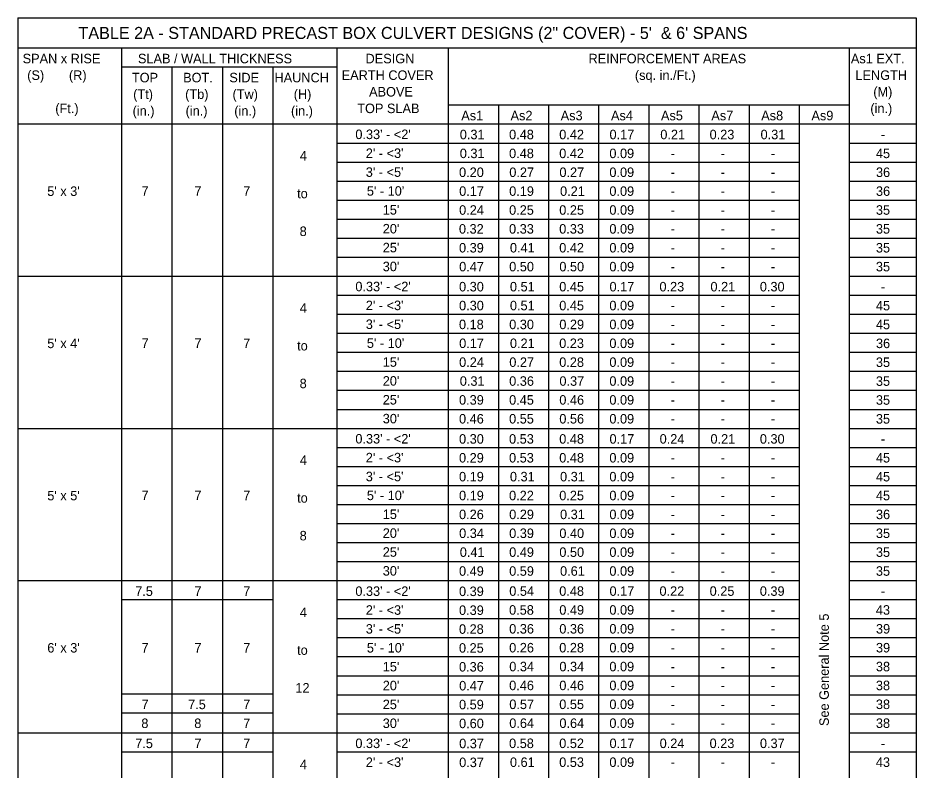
# Model space of a CAD drawing. Extents: x 10340.93 to 10343.14, y 76399.51 to 76400.59.
# Drawn here: x 10340.938 to 10341.533, y 76400.002 to 76400.5 of the extents above; entities that cross this region are included whole.
import ezdxf

# ---------------------------------------------------------------- set-up
doc = ezdxf.new("R2010")
doc.units = 0
doc.layers.add('AdhocPoint_dp', color=7, linetype='Continuous')
doc.layers.add('PlotBorder_dp', color=7, linetype='Continuous')

msp = doc.modelspace()

# ---------------------------------------------------------------- linework, layer by layer
at = {"layer": 'PlotBorder_dp'}
for p, q in [((10340.93815, 76400.49971), (10341.53289, 76400.49971)), ((10340.93815, 76400.49971), (10340.93815, 76399.72389)), ((10341.53289, 76400.49971), (10341.53289, 76399.72389)), ((10340.93815, 76400.47984), (10341.53289, 76400.47984)), ((10341.00679, 76400.47984), (10341.00679, 76399.72389)), ((10341.14923, 76400.47984), (10341.14923, 76399.72389)), ((10341.22311, 76400.47984), (10341.22311, 76399.72389)), ((10341.4887, 76400.47984), (10341.4887, 76399.72389)), ((10341.00679, 76400.46724), (10341.14923, 76400.46724)), ((10341.04015, 76400.46724), (10341.04015, 76399.72389)), ((10341.07351, 76400.46724), (10341.07351, 76399.72389)), ((10341.10687, 76400.46724), (10341.10687, 76399.72389)), ((10341.22311, 76400.44209), (10341.4887, 76400.44209)), ((10341.25631, 76400.44209), (10341.25631, 76399.72389)), ((10341.28951, 76400.44209), (10341.28951, 76399.72389)), ((10341.32271, 76400.44209), (10341.32271, 76399.72389)), ((10341.35591, 76400.44209), (10341.35591, 76399.72389)), ((10341.3891, 76400.44209), (10341.3891, 76399.72389)), ((10341.3891, 76400.44209), (10341.3891, 76399.72389)), ((10341.4223, 76400.44209), (10341.4223, 76399.72389)), ((10341.4555, 76400.44209), (10341.4555, 76399.72389)), ((10340.93815, 76400.42949), (10341.53289, 76400.42949)), ((10341.14923, 76400.41689), (10341.4555, 76400.41689)), ((10341.4887, 76400.41689), (10341.53289, 76400.41689)), ((10341.14923, 76400.40429), (10341.4555, 76400.40429)), ((10341.4887, 76400.40429), (10341.53289, 76400.40429)), ((10341.14923, 76400.39169), (10341.4555, 76400.39169)), ((10341.4887, 76400.39169), (10341.53289, 76400.39169)), ((10341.14923, 76400.37909), (10341.4555, 76400.37909)), ((10341.4887, 76400.37909), (10341.53289, 76400.37909)), ((10341.14923, 76400.36649), (10341.4555, 76400.36649)), ((10341.4887, 76400.36649), (10341.53289, 76400.36649)), ((10341.14923, 76400.35389), (10341.4555, 76400.35389)), ((10341.4887, 76400.35389), (10341.53289, 76400.35389)), ((10341.14923, 76400.34129), (10341.4555, 76400.34129)), ((10341.4887, 76400.34129), (10341.53289, 76400.34129)), ((10340.93815, 76400.32869), (10341.4555, 76400.32869)), ((10341.4887, 76400.32869), (10341.53289, 76400.32869)), ((10341.14923, 76400.31609), (10341.4555, 76400.31609)), ((10341.4887, 76400.31609), (10341.53289, 76400.31609)), ((10341.14923, 76400.30349), (10341.4555, 76400.30349)), ((10341.4887, 76400.30349), (10341.53289, 76400.30349)), ((10341.14923, 76400.29089), (10341.4555, 76400.29089)), ((10341.4887, 76400.29089), (10341.53289, 76400.29089)), ((10341.14923, 76400.27829), (10341.4555, 76400.27829)), ((10341.4887, 76400.27829), (10341.53289, 76400.27829)), ((10341.14923, 76400.26569), (10341.4555, 76400.26569)), ((10341.4887, 76400.26569), (10341.53289, 76400.26569)), ((10341.14923, 76400.25309), (10341.4555, 76400.25309)), ((10341.4887, 76400.25309), (10341.53289, 76400.25309)), ((10341.14923, 76400.24049), (10341.4555, 76400.24049)), ((10341.4887, 76400.24049), (10341.53289, 76400.24049)), ((10340.93815, 76400.22789), (10341.4555, 76400.22789)), ((10341.4887, 76400.22789), (10341.53289, 76400.22789)), ((10341.14923, 76400.21529), (10341.4555, 76400.21529)), ((10341.4887, 76400.21529), (10341.53289, 76400.21529)), ((10341.14923, 76400.20269), (10341.4555, 76400.20269)), ((10341.4887, 76400.20269), (10341.53289, 76400.20269)), ((10341.14923, 76400.19009), (10341.4555, 76400.19009)), ((10341.4887, 76400.19009), (10341.53289, 76400.19009)), ((10341.14923, 76400.17749), (10341.4555, 76400.17749)), ((10341.4887, 76400.17749), (10341.53289, 76400.17749)), ((10341.14923, 76400.16489), (10341.4555, 76400.16489)), ((10341.4887, 76400.16489), (10341.53289, 76400.16489)), ((10341.14923, 76400.15229), (10341.4555, 76400.15229)), ((10341.4887, 76400.15229), (10341.53289, 76400.15229)), ((10341.14923, 76400.13969), (10341.4555, 76400.13969)), ((10341.4887, 76400.13969), (10341.53289, 76400.13969)), ((10340.93815, 76400.12709), (10341.4555, 76400.12709)), ((10341.4887, 76400.12709), (10341.53289, 76400.12709)), ((10341.00679, 76400.11449), (10341.10687, 76400.11449)), ((10341.14923, 76400.11449), (10341.4555, 76400.11449)), ((10341.4887, 76400.11449), (10341.53289, 76400.11449)), ((10341.14923, 76400.10189), (10341.4555, 76400.10189)), ((10341.4887, 76400.10189), (10341.53289, 76400.10189)), ((10341.14923, 76400.08929), (10341.4555, 76400.08929)), ((10341.4887, 76400.08929), (10341.53289, 76400.08929)), ((10341.14923, 76400.07669), (10341.4555, 76400.07669)), ((10341.4887, 76400.07669), (10341.53289, 76400.07669)), ((10341.14923, 76400.06409), (10341.4555, 76400.06409)), ((10341.4887, 76400.06409), (10341.53289, 76400.06409)), ((10341.00679, 76400.05197), (10341.10687, 76400.05197)), ((10341.14923, 76400.05149), (10341.4555, 76400.05149)), ((10341.4887, 76400.05149), (10341.53289, 76400.05149)), ((10341.00679, 76400.03947), (10341.10687, 76400.03947)), ((10341.14923, 76400.03889), (10341.4555, 76400.03889)), ((10341.4887, 76400.03889), (10341.53289, 76400.03889)), ((10340.93815, 76400.02629), (10341.4555, 76400.02629)), ((10341.14985, 76400.02629), (10341.22203, 76400.02629)), ((10341.4887, 76400.02629), (10341.53289, 76400.02629)), ((10341.00679, 76400.01369), (10341.10687, 76400.01369)), ((10341.14923, 76400.01369), (10341.4555, 76400.01369)), ((10341.4887, 76400.01369), (10341.53289, 76400.01369))]:
    msp.add_line(p, q, dxfattribs=at)

# ---------------------------------------------------------------- texts
at = {"layer": 'AdhocPoint_dp'}
for s, height, p in [('TABLE 2A - STANDARD PRECAST BOX CULVERT DESIGNS (2" COVER) - 5\'  & 6\' SPANS', 0.008, (10340.97821, 76400.48578)), ('SLAB / WALL THICKNESS', 0.0063, (10341.01761, 76400.46968)), ('As1', 0.0063, (10341.23173, 76400.43192)), ('As2', 0.0063, (10341.26436, 76400.43192)), ('As3', 0.0063, (10341.29756, 76400.43192)), ('As4', 0.0063, (10341.33089, 76400.43192)), ('As5', 0.0063, (10341.36398, 76400.43192)), ('As7', 0.0063, (10341.39733, 76400.43192)), ('As8', 0.0063, (10341.43037, 76400.43192)), ('As9', 0.0063, (10341.46362, 76400.43192)), ("5' x 3'", 0.0063, (10340.95757, 76400.38182)), ("5' x 4'", 0.0063, (10340.95756, 76400.28104)), ("5' x 5'", 0.0063, (10340.95758, 76400.1802))]:
    msp.add_text(s, height=height, dxfattribs=at).set_placement(p)
msp.add_text('See General Note 5', height=0.0063, rotation=90, dxfattribs=at).set_placement((10341.47515, 76400.03075))
at = {"layer": 'PlotBorder_dp'}
for s, p in [('SPAN x RISE', (10340.94124, 76400.46968)), ('DESIGN', (10341.16833, 76400.46968)), ('REINFORCEMENT AREAS', (10341.31601, 76400.46968)), ('(S)       (R)', (10340.94428, 76400.45868)), ('EARTH COVER', (10341.15254, 76400.45868)), ('(sq. in./Ft.)', (10341.34671, 76400.45868)), ('TOP', (10341.01361, 76400.45708)), ('BOT.', (10341.04754, 76400.45708)), ('SIDE', (10341.07814, 76400.45708)), ('HAUNCH', (10341.10803, 76400.45708)), ('ABOVE', (10341.17068, 76400.44768)), ('(Tt)', (10341.01446, 76400.44608)), ('(Tb)', (10341.04888, 76400.44608)), ('(Tw)', (10341.08024, 76400.44608)), ('(H)', (10341.12077, 76400.44608)), ('(Ft.)', (10340.96286, 76400.43668)), ('(in.)', (10341.01407, 76400.43508)), ('(in.)', (10341.04916, 76400.43508)), ('(in.)', (10341.08139, 76400.43508)), ('(in.)', (10341.11896, 76400.43508)), ('TOP SLAB', (10341.16285, 76400.43668)), ("0.33' - <2'", (10341.16159, 76400.41948)), ('0.31', (10341.23075, 76400.41937)), ('0.48', (10341.2634, 76400.41937)), ('0.42', (10341.29659, 76400.41937)), ('0.17', (10341.32989, 76400.41937)), ('0.21', (10341.36354, 76400.41937)), ('0.23', (10341.39618, 76400.41937)), ('0.31', (10341.42994, 76400.41937)), ('-', (10341.50962, 76400.41937)), ('4', (10341.12481, 76400.40529)), ("2' - <3'", (10341.16849, 76400.40698)), ('0.31', (10341.23075, 76400.40687)), ('0.48', (10341.2634, 76400.40687)), ('0.42', (10341.29659, 76400.40687)), ('0.09', (10341.32981, 76400.40687)), ('45', (10341.50632, 76400.40687)), ('-', (10341.37038, 76400.40687)), ('-', (10341.40359, 76400.40687)), ('-', (10341.43677, 76400.40687)), ("3' - <5'", (10341.16849, 76400.39448)), ('0.20', (10341.23027, 76400.39437)), ('0.27', (10341.26353, 76400.39437)), ('0.27', (10341.29673, 76400.39437)), ('0.09', (10341.32981, 76400.39437)), ('36', (10341.50636, 76400.39437)), ('-', (10341.37038, 76400.39437)), ('-', (10341.40359, 76400.39437)), ('-', (10341.43677, 76400.39437)), ('7', (10341.01998, 76400.38198)), ('7', (10341.05502, 76400.38198)), ('7', (10341.08731, 76400.38192)), ("5' - 10'", (10341.1692, 76400.38198)), ('0.17', (10341.23033, 76400.38187)), ('0.19', (10341.26345, 76400.38187)), ('0.21', (10341.29715, 76400.38187)), ('0.09', (10341.32981, 76400.38187)), ('36', (10341.50636, 76400.38187)), ('to', (10341.12303, 76400.38029)), ('-', (10341.37038, 76400.38187)), ('-', (10341.40359, 76400.38187)), ('-', (10341.43677, 76400.38187)), ("15'", (10341.17972, 76400.36948)), ('0.24', (10341.23031, 76400.36937)), ('0.25', (10341.26341, 76400.36937)), ('0.25', (10341.29661, 76400.36937)), ('0.09', (10341.32981, 76400.36937)), ('35', (10341.50632, 76400.36937)), ('-', (10341.37038, 76400.36937)), ('-', (10341.40359, 76400.36937)), ('-', (10341.43677, 76400.36937)), ('8', (10341.1247, 76400.35529)), ("20'", (10341.17972, 76400.35698)), ('0.32', (10341.23019, 76400.35687)), ('0.33', (10341.26338, 76400.35687)), ('0.33', (10341.29658, 76400.35687)), ('0.09', (10341.32981, 76400.35687)), ('-', (10341.37038, 76400.35687)), ('-', (10341.40359, 76400.35687)), ('-', (10341.43677, 76400.35687)), ('35', (10341.50632, 76400.35687)), ("25'", (10341.17972, 76400.34448)), ('0.39', (10341.23025, 76400.34437)), ('0.41', (10341.26395, 76400.34437)), ('0.42', (10341.29659, 76400.34437)), ('0.09', (10341.32981, 76400.34437)), ('-', (10341.37038, 76400.34437)), ('-', (10341.40359, 76400.34437)), ('-', (10341.43677, 76400.34437)), ('35', (10341.50632, 76400.34437)), ("30'", (10341.17972, 76400.33198)), ('0.47', (10341.23033, 76400.33187)), ('0.50', (10341.26346, 76400.33187)), ('0.50', (10341.29667, 76400.33187)), ('0.09', (10341.32981, 76400.33187)), ('-', (10341.37038, 76400.33187)), ('-', (10341.40359, 76400.33187)), ('-', (10341.43677, 76400.33187)), ('35', (10341.50632, 76400.33187)), ("0.33' - <2'", (10341.16159, 76400.31869)), ('0.30', (10341.23027, 76400.31859)), ('0.51', (10341.26395, 76400.31859)), ('0.45', (10341.29661, 76400.31859)), ('0.17', (10341.32989, 76400.31859)), ('0.23', (10341.36297, 76400.31859)), ('0.21', (10341.39675, 76400.31859)), ('0.30', (10341.42945, 76400.31859)), ('-', (10341.50962, 76400.31854)), ('4', (10341.12481, 76400.30449)), ("2' - <3'", (10341.16849, 76400.30619)), ('0.30', (10341.23027, 76400.30609)), ('0.51', (10341.26395, 76400.30609)), ('0.45', (10341.29661, 76400.30609)), ('0.09', (10341.32981, 76400.30609)), ('45', (10341.50632, 76400.30604)), ('-', (10341.37038, 76400.30609)), ('-', (10341.40359, 76400.30609)), ('-', (10341.43677, 76400.30609)), ("3' - <5'", (10341.16849, 76400.29369)), ('0.18', (10341.23021, 76400.29359)), ('0.30', (10341.26346, 76400.29359)), ('0.29', (10341.29665, 76400.29359)), ('0.09', (10341.32981, 76400.29359)), ('45', (10341.50632, 76400.29354)), ('-', (10341.37038, 76400.29359)), ('-', (10341.40359, 76400.29359)), ('-', (10341.43677, 76400.29359)), ('7', (10341.01998, 76400.28114)), ('7', (10341.05502, 76400.28114)), ('7', (10341.08731, 76400.28109)), ("5' - 10'", (10341.1692, 76400.28119)), ('0.17', (10341.23033, 76400.28109)), ('0.21', (10341.26395, 76400.28109)), ('0.23', (10341.29658, 76400.28109)), ('0.09', (10341.32981, 76400.28109)), ('36', (10341.50636, 76400.28104)), ('to', (10341.12303, 76400.27949)), ('-', (10341.37038, 76400.28109)), ('-', (10341.40359, 76400.28109)), ('-', (10341.43677, 76400.28109)), ("15'", (10341.17972, 76400.26869)), ('0.24', (10341.23031, 76400.26859)), ('0.27', (10341.26353, 76400.26859)), ('0.28', (10341.2966, 76400.26859)), ('0.09', (10341.32981, 76400.26859)), ('35', (10341.50632, 76400.26854)), ('-', (10341.37038, 76400.26859)), ('-', (10341.40359, 76400.26859)), ('-', (10341.43677, 76400.26859)), ('8', (10341.1247, 76400.25449)), ("20'", (10341.17972, 76400.25619)), ('0.31', (10341.23075, 76400.25609)), ('0.36', (10341.26345, 76400.25609)), ('0.37', (10341.29673, 76400.25609)), ('0.09', (10341.32981, 76400.25609)), ('-', (10341.37038, 76400.25609)), ('-', (10341.40359, 76400.25609)), ('-', (10341.43677, 76400.25609)), ('35', (10341.50632, 76400.25604)), ("25'", (10341.17972, 76400.24369)), ('0.39', (10341.23025, 76400.24359)), ('0.45', (10341.26341, 76400.24359)), ('0.46', (10341.29665, 76400.24359)), ('0.09', (10341.32981, 76400.24359)), ('-', (10341.37038, 76400.24359)), ('-', (10341.40359, 76400.24359)), ('-', (10341.43677, 76400.24359)), ('35', (10341.50632, 76400.24354)), ("30'", (10341.17972, 76400.23119)), ('0.46', (10341.23025, 76400.23109)), ('0.55', (10341.26341, 76400.23109)), ('0.56', (10341.29665, 76400.23109)), ('0.09', (10341.32981, 76400.23109)), ('-', (10341.37038, 76400.23109)), ('-', (10341.40359, 76400.23109)), ('-', (10341.43677, 76400.23109)), ('35', (10341.50632, 76400.23104)), ("0.33' - <2'", (10341.16159, 76400.21786)), ('0.30', (10341.23027, 76400.21776)), ('0.53', (10341.26338, 76400.21776)), ('0.48', (10341.2966, 76400.21776)), ('0.17', (10341.32989, 76400.21776)), ('0.24', (10341.3631, 76400.21776)), ('0.21', (10341.39675, 76400.21776)), ('0.30', (10341.42945, 76400.21776)), ('-', (10341.50962, 76400.21776)), ('4', (10341.12481, 76400.20369)), ("2' - <3'", (10341.16849, 76400.20536)), ('0.29', (10341.23025, 76400.20526)), ('0.53', (10341.26338, 76400.20526)), ('0.48', (10341.2966, 76400.20526)), ('0.09', (10341.32981, 76400.20526)), ('45', (10341.50632, 76400.20526)), ('-', (10341.37038, 76400.20526)), ('-', (10341.40359, 76400.20526)), ('-', (10341.43677, 76400.20526)), ("3' - <5'", (10341.16849, 76400.19286)), ('0.19', (10341.23025, 76400.19276)), ('0.31', (10341.26395, 76400.19276)), ('0.31', (10341.29715, 76400.19276)), ('0.09', (10341.32981, 76400.19276)), ('45', (10341.50632, 76400.19276)), ('-', (10341.37038, 76400.19276)), ('-', (10341.40359, 76400.19276)), ('-', (10341.43677, 76400.19276)), ('7', (10341.01998, 76400.18036)), ('7', (10341.05502, 76400.18036)), ('7', (10341.08731, 76400.18031)), ("5' - 10'", (10341.1692, 76400.18036)), ('0.19', (10341.23025, 76400.18026)), ('0.22', (10341.26339, 76400.18026)), ('0.25', (10341.29661, 76400.18026)), ('0.09', (10341.32981, 76400.18026)), ('45', (10341.50632, 76400.18026)), ('to', (10341.12303, 76400.17869)), ('-', (10341.37038, 76400.18026)), ('-', (10341.40359, 76400.18026)), ('-', (10341.43677, 76400.18026)), ("15'", (10341.17972, 76400.16786)), ('0.26', (10341.23025, 76400.16776)), ('0.29', (10341.26345, 76400.16776)), ('0.31', (10341.29715, 76400.16776)), ('0.09', (10341.32981, 76400.16776)), ('36', (10341.50636, 76400.16776)), ('-', (10341.37038, 76400.16776)), ('-', (10341.40359, 76400.16776)), ('-', (10341.43677, 76400.16776)), ("20'", (10341.17972, 76400.15536)), ('0.34', (10341.23031, 76400.15526)), ('0.39', (10341.26345, 76400.15526)), ('0.40', (10341.29667, 76400.15526)), ('0.09', (10341.32981, 76400.15526)), ('35', (10341.50632, 76400.15526)), ('8', (10341.1247, 76400.15369)), ('-', (10341.37038, 76400.15526)), ('-', (10341.40359, 76400.15526)), ('-', (10341.43677, 76400.15526)), ("25'", (10341.17972, 76400.14286)), ('0.41', (10341.23075, 76400.14276)), ('0.49', (10341.26345, 76400.14276)), ('0.50', (10341.29667, 76400.14276)), ('0.09', (10341.32981, 76400.14276)), ('-', (10341.37038, 76400.14276)), ('-', (10341.40359, 76400.14276)), ('-', (10341.43677, 76400.14276)), ('35', (10341.50632, 76400.14276)), ("30'", (10341.17972, 76400.13036)), ('0.49', (10341.23025, 76400.13026)), ('0.59', (10341.26345, 76400.13026)), ('0.61', (10341.29715, 76400.13026)), ('0.09', (10341.32981, 76400.13026)), ('-', (10341.37038, 76400.13026)), ('-', (10341.40359, 76400.13026)), ('-', (10341.43677, 76400.13026)), ('35', (10341.50632, 76400.13026)), ('7.5', (10341.0158, 76400.11692)), ('7', (10341.05502, 76400.11692)), ('7', (10341.08731, 76400.11692)), ("0.33' - <2'", (10341.16159, 76400.11692)), ('0.39', (10341.23025, 76400.11682)), ('0.54', (10341.26351, 76400.11698)), ('0.48', (10341.2966, 76400.11698)), ('0.17', (10341.32989, 76400.11698)), ('0.22', (10341.36298, 76400.11698)), ('0.25', (10341.39621, 76400.11698)), ('0.39', (10341.42943, 76400.11698)), ('-', (10341.50962, 76400.11698)), ('4', (10341.12481, 76400.10289)), ("2' - <3'", (10341.16849, 76400.10442)), ('0.39', (10341.23025, 76400.10432)), ('0.58', (10341.2634, 76400.10448)), ('0.49', (10341.29665, 76400.10448)), ('0.09', (10341.32981, 76400.10448)), ('43', (10341.50629, 76400.10448)), ('-', (10341.37038, 76400.10448)), ('-', (10341.40359, 76400.10448)), ('-', (10341.43677, 76400.10448)), ("3' - <5'", (10341.16849, 76400.09192)), ('0.28', (10341.23021, 76400.09182)), ('0.36', (10341.26345, 76400.09198)), ('0.36', (10341.29665, 76400.09198)), ('0.09', (10341.32981, 76400.09198)), ('39', (10341.50636, 76400.09198)), ('-', (10341.37038, 76400.09198)), ('-', (10341.40359, 76400.09198)), ('-', (10341.43677, 76400.09198)), ("6' x 3'", (10340.95759, 76400.07942)), ('7', (10341.01998, 76400.07942)), ('7', (10341.05502, 76400.07942)), ('7', (10341.08731, 76400.07942)), ("5' - 10'", (10341.1692, 76400.07942)), ('0.25', (10341.23021, 76400.07932)), ('0.26', (10341.26345, 76400.07948)), ('0.28', (10341.2966, 76400.07948)), ('0.09', (10341.32981, 76400.07948)), ('39', (10341.50636, 76400.07948)), ('to', (10341.12303, 76400.07789)), ('-', (10341.37038, 76400.07948)), ('-', (10341.40359, 76400.07948)), ('-', (10341.43677, 76400.07948)), ("15'", (10341.17972, 76400.06692)), ('0.36', (10341.23025, 76400.06682)), ('0.34', (10341.26351, 76400.06698)), ('0.34', (10341.29671, 76400.06698)), ('0.09', (10341.32981, 76400.06698)), ('38', (10341.50631, 76400.06698)), ('-', (10341.37038, 76400.06698)), ('-', (10341.40359, 76400.06698)), ('-', (10341.43677, 76400.06698)), ("20'", (10341.17972, 76400.05442)), ('0.47', (10341.23033, 76400.05432)), ('0.46', (10341.26345, 76400.05448)), ('0.46', (10341.29665, 76400.05448)), ('0.09', (10341.32981, 76400.05448)), ('38', (10341.50631, 76400.05448)), ('12', (10341.12186, 76400.05289)), ('-', (10341.37038, 76400.05448)), ('-', (10341.40359, 76400.05448)), ('-', (10341.43677, 76400.05448)), ('7', (10341.01998, 76400.04192)), ('7.5', (10341.05084, 76400.04192)), ('7', (10341.08731, 76400.04192)), ("25'", (10341.17972, 76400.04192)), ('0.59', (10341.23025, 76400.04182)), ('0.57', (10341.26353, 76400.04198)), ('0.55', (10341.29661, 76400.04198)), ('0.09', (10341.32981, 76400.04198)), ('-', (10341.37038, 76400.04198)), ('-', (10341.40359, 76400.04198)), ('-', (10341.43677, 76400.04198)), ('38', (10341.50631, 76400.04198)), ('8', (10341.01986, 76400.02942)), ('8', (10341.0549, 76400.02942)), ('7', (10341.08731, 76400.02942)), ("30'", (10341.17972, 76400.02942)), ('0.60', (10341.23027, 76400.02932)), ('0.64', (10341.26351, 76400.02948)), ('0.64', (10341.29671, 76400.02948)), ('0.09', (10341.32981, 76400.02948)), ('-', (10341.37038, 76400.02948)), ('-', (10341.40359, 76400.02948)), ('-', (10341.43677, 76400.02948)), ('38', (10341.50631, 76400.02948)), ('7.5', (10341.0158, 76400.01612)), ('7', (10341.05502, 76400.01612)), ('7', (10341.08731, 76400.01612)), ("0.33' - <2'", (10341.16159, 76400.01614)), ('0.37', (10341.23033, 76400.01604)), ('0.58', (10341.2634, 76400.01614)), ('0.52', (10341.29659, 76400.01614)), ('0.17', (10341.32989, 76400.01614)), ('0.24', (10341.3631, 76400.01614)), ('0.23', (10341.39618, 76400.01614)), ('0.37', (10341.42951, 76400.01614)), ('-', (10341.50962, 76400.01614)), ('4', (10341.12481, 76400.00209)), ("2' - <3'", (10341.16849, 76400.00364)), ('0.37', (10341.23033, 76400.00354)), ('0.61', (10341.26395, 76400.00364)), ('0.53', (10341.29658, 76400.00364)), ('0.09', (10341.32981, 76400.00364)), ('43', (10341.50629, 76400.00364)), ('-', (10341.37038, 76400.00364)), ('-', (10341.40359, 76400.00364)), ('-', (10341.43677, 76400.00364))]:
    msp.add_text(s, height=0.0063, dxfattribs=at).set_placement(p)
for s, p in [('As1 EXT.', (10341.48975, 76400.46968)), ('LENGTH', (10341.49277, 76400.45868)), ('(M)', (10341.50458, 76400.44768)), ('(in.)', (10341.50262, 76400.43668))]:
    msp.add_text(s, height=0.0063, rotation=360, dxfattribs=at).set_placement(p)

doc.saveas('drawing.dxf')
